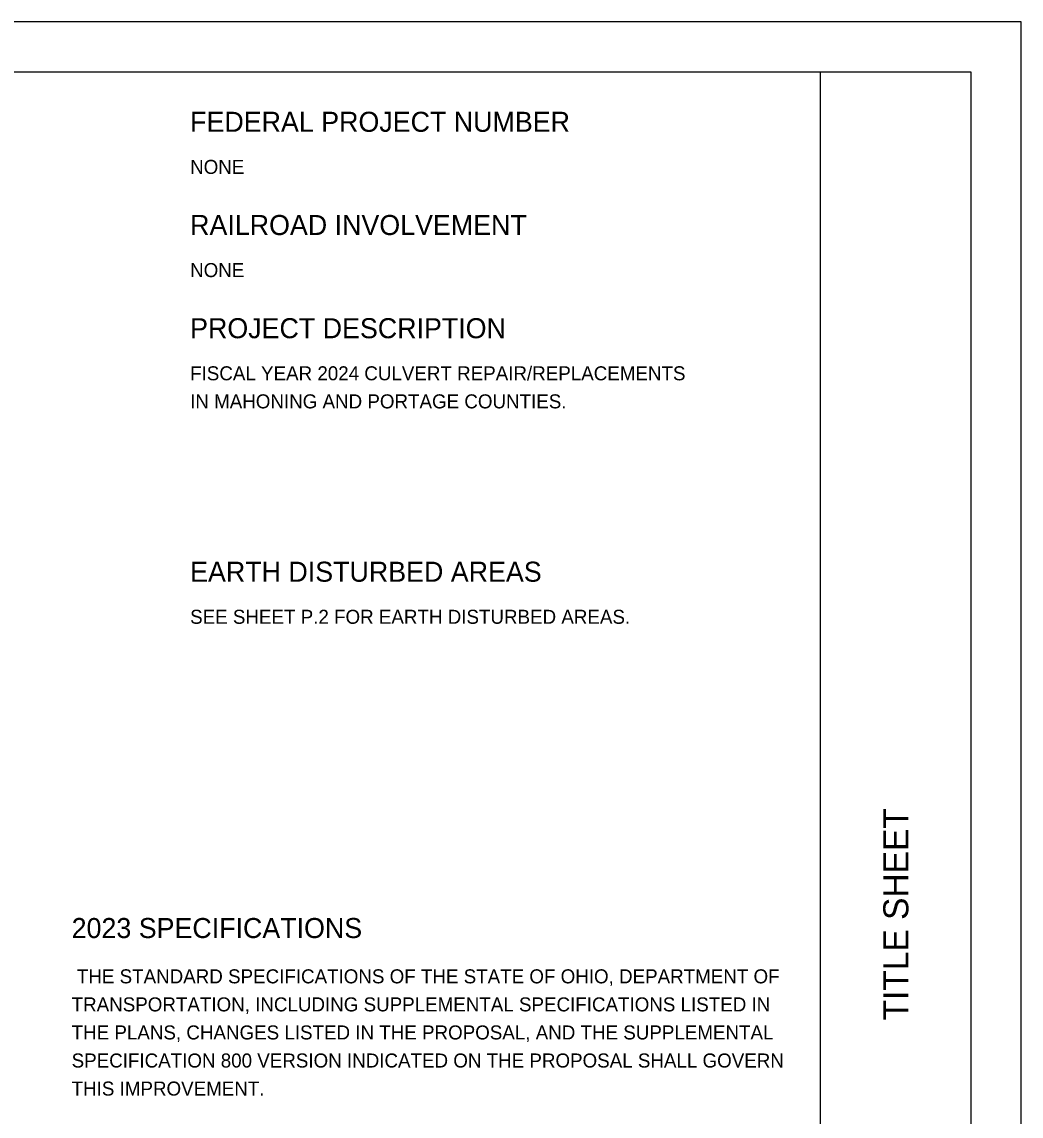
# Model space of a CAD drawing. Extents: x 0 to 34, y 0 to 22.
# Drawn here: x 24.03 to 34, y 11.08 to 22 of the extents above; entities that cross this region are included whole.
import ezdxf

# ---------------------------------------------------------------- set-up
doc = ezdxf.new("R2010")
doc.units = 0
for name, color, linetype in [('SH_Border', 7, 'Continuous'), ('SH_Cut_Line', 7, 'Continuous'), ('SH_Data', 7, 'Continuous'), ('SH_Text', 7, 'Continuous')]:
    doc.layers.add(name, color=color, linetype=linetype)

msp = doc.modelspace()

# ---------------------------------------------------------------- linework, layer by layer
at = {"layer": 'SH_Border'}
msp.add_line((32, 0.5), (32, 21.5), dxfattribs=at)
msp.add_lwpolyline([(1.5, 21.5), (33.5, 21.5), (33.5, 0.5), (1.5, 0.5)], close=True, dxfattribs=at)
at = {"layer": 'SH_Cut_Line'}
msp.add_lwpolyline([(0, 0), (34, 0), (34, 22), (0, 22)], close=True, dxfattribs=at)

# ---------------------------------------------------------------- texts
at = {"layer": 'SH_Data'}
msp.add_text('TITLE SHEET', height=0.25, rotation=90, dxfattribs=at).set_placement((32.875, 12.035))
at = {"layer": 'SH_Text'}
for s, height, p in [('FEDERAL PROJECT NUMBER', 0.2, (25.71, 20.903)), ('NONE      ', 0.14, (25.71, 20.483)), ('RAILROAD INVOLVEMENT', 0.2, (25.71, 19.873)), ('NONE                ', 0.14, (25.71, 19.453)), ('PROJECT DESCRIPTION', 0.2, (25.71, 18.843)), ('FISCAL YEAR 2024 CULVERT REPAIR/REPLACEMENTS           ', 0.14, (25.71, 18.423)), ('IN MAHONING AND PORTAGE COUNTIES.                      ', 0.14, (25.71, 18.143)), ('EARTH DISTURBED AREAS', 0.2, (25.71, 16.413)), ('SEE SHEET P.2 FOR EARTH DISTURBED AREAS.', 0.14, (25.71, 15.993)), ('2023 SPECIFICATIONS', 0.2, (24.528, 12.857)), (' THE STANDARD SPECIFICATIONS OF THE STATE OF OHIO, DEPARTMENT OF', 0.14, (24.528, 12.405)), ('TRANSPORTATION, INCLUDING SUPPLEMENTAL SPECIFICATIONS LISTED IN', 0.14, (24.528, 12.125)), ('THE PLANS, CHANGES LISTED IN THE PROPOSAL, AND THE SUPPLEMENTAL', 0.14, (24.528, 11.845)), ('SPECIFICATION 800 VERSION INDICATED ON THE PROPOSAL SHALL GOVERN', 0.14, (24.528, 11.565)), ('THIS IMPROVEMENT.', 0.14, (24.528, 11.285))]:
    msp.add_text(s, height=height, dxfattribs=at).set_placement(p)

doc.saveas('drawing.dxf')
